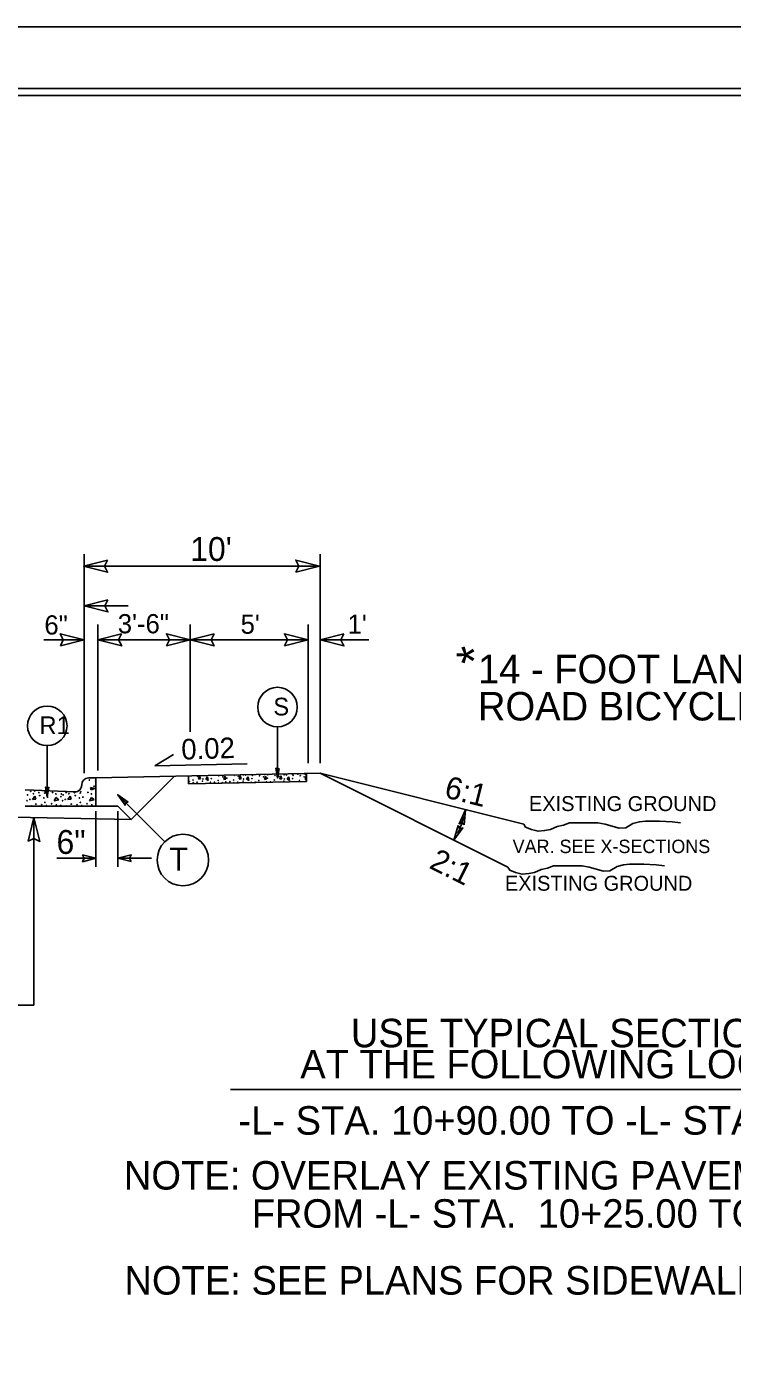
# Model space of a CAD drawing. Extents: x 573786 to 574032, y -53324 to -53148.
# Drawn here: x 573965.38 to 573991.09, y -53263.27 to -53214.45 of the extents above; entities that cross this region are included whole.
import ezdxf

# ---------------------------------------------------------------- set-up
doc = ezdxf.new("R2010")
doc.units = 0
for name, color, linetype in [('Default', 7, 'Continuous'), ('Prop Dimension Text', 7, 'Continuous'), ('Sheet Cutting Line CELL', 7, 'Continuous'), ('Sheet Plot Border Inside CELL', 7, 'Continuous'), ('Sheet Plot Border Outside CELL', 7, 'Continuous'), ('Sheet Typical CELL', 7, 'Continuous'), ('Typical Berm CELL', 7, 'Continuous'), ('Typical Berm Information CELL', 7, 'Continuous'), ('Typical Curb CELL', 7, 'Continuous'), ('Typical ID Circle CELL', 7, 'Continuous'), ('Typical Pavement Slope Information CELL', 7, 'Continuous'), ('Typical Slope Point Local CELL', 7, 'Continuous'), ('Typical Terminator CELL', 7, 'Continuous'), ('Typical Text ID Circle CELL', 7, 'Continuous'), ('Typical Text Label CELL', 7, 'Continuous')]:
    doc.layers.add(name, color=color, linetype=linetype)

# ---------------------------------------------------------------- blocks, each defined once
blk = doc.blocks.new('TERMINATOR')
at = {"layer": 'Typical Terminator CELL'}
blk.add_lwpolyline([(-0.469, 0.081), (0, 0), (-0.471, -0.083), (-0.411, 0)], close=True, dxfattribs=at)

msp = doc.modelspace()

# ---------------------------------------------------------------- linework, layer by layer
at = {"layer": 'Default'}
for points in [[(573989.198, -53243.465), (573988.895, -53243.421), (573988.442, -53243.4), (573988.139, -53243.4), (573987.923, -53243.4), (573987.707, -53243.421), (573987.469, -53243.486), (573987.21, -53243.638), (573986.973, -53243.659), (573986.67, -53243.573), (573986.454, -53243.508), (573986.195, -53243.465), (573985.892, -53243.465), (573985.655, -53243.465), (573985.417, -53243.465), (573985.158, -53243.465), (573984.942, -53243.551), (573984.704, -53243.594), (573984.466, -53243.702), (573984.25, -53243.746), (573984.012, -53243.767), (573983.775, -53243.702), (573983.559, -53243.616), (573983.494, -53243.508)], [(573988.618, -53245.032), (573988.316, -53244.988), (573987.862, -53244.967), (573987.56, -53244.967), (573987.344, -53244.967), (573987.127, -53244.988), (573986.89, -53245.053), (573986.631, -53245.205), (573986.393, -53245.226), (573986.09, -53245.14), (573985.874, -53245.075), (573985.615, -53245.032), (573985.313, -53245.032), (573985.075, -53245.032), (573984.837, -53245.032), (573984.578, -53245.032), (573984.362, -53245.118), (573984.124, -53245.161), (573983.887, -53245.269), (573983.671, -53245.313), (573983.433, -53245.334), (573983.195, -53245.269), (573982.979, -53245.183), (573982.914, -53245.075)]]:
    msp.add_lwpolyline(points, dxfattribs=at)
at = {"layer": 'Prop Dimension Text'}
for p, q in [((573967.47, -53241.655), (573967.47, -53233.673)), ((573976.067, -53241.285), (573976.067, -53233.673)), ((573967.47, -53234.106), (573976.052, -53234.105)), ((573967.47, -53235.551), (573969.076, -53235.55)), ((573967.971, -53241.548), (573967.971, -53236.228)), ((573971.339, -53240.145), (573971.338, -53236.228)), ((573975.637, -53241.285), (573975.637, -53236.228)), ((573966.004, -53236.792), (573967.47, -53236.792)), ((573967.971, -53236.792), (573975.637, -53236.792)), ((573976.067, -53236.792), (573977.84, -53236.792)), ((573971.676, -53241.747), (573971.641, -53241.869)), ((573971.713, -53241.855), (573971.676, -53241.747)), ((573971.905, -53241.862), (573971.963, -53241.781)), ((573971.963, -53241.781), (573971.995, -53241.912)), ((573972.595, -53241.762), (573972.56, -53241.885)), ((573972.632, -53241.871), (573972.595, -53241.762)), ((573973.158, -53241.747), (573973.122, -53241.869)), ((573973.194, -53241.855), (573973.158, -53241.747)), ((573973.386, -53241.862), (573973.445, -53241.781)), ((573973.445, -53241.781), (573973.476, -53241.912)), ((573974.077, -53241.762), (573974.041, -53241.885)), ((573974.114, -53241.871), (573974.077, -53241.762)), ((573974.639, -53241.747), (573974.604, -53241.869)), ((573974.676, -53241.855), (573974.639, -53241.747)), ((573974.868, -53241.862), (573974.926, -53241.781)), ((573974.926, -53241.781), (573974.958, -53241.912)), ((573975.558, -53241.762), (573975.523, -53241.885)), ((573975.569, -53241.794), (573975.558, -53241.762)), ((573971.342, -53242.037), (573971.342, -53242.037)), ((573971.342, -53242.037), (573971.342, -53242.037)), ((573971.641, -53241.869), (573971.713, -53241.855)), ((573971.995, -53241.912), (573971.905, -53241.862)), ((573972.56, -53241.885), (573972.632, -53241.871)), ((573973.122, -53241.869), (573973.194, -53241.855)), ((573973.476, -53241.912), (573973.386, -53241.862)), ((573974.041, -53241.885), (573974.114, -53241.871)), ((573974.604, -53241.869), (573974.676, -53241.855)), ((573974.958, -53241.912), (573974.868, -53241.862)), ((573975.523, -53241.885), (573975.569, -53241.876)), ((573965.642, -53250.111), (573965.641, -53243.269)), ((573967.903, -53245.07), (573967.903, -53243.039)), ((573968.701, -53245.07), (573968.701, -53243.039)), ((573967.903, -53244.753), (573966.471, -53244.753)), ((573969.921, -53244.753), (573968.701, -53244.753)), ((573965.642, -53250.111), (573957.762, -53250.111))]:
    msp.add_line(p, q, dxfattribs=at)
for centre in [(573971.609, -53241.77), (573972.383, -53241.745), (573972.528, -53241.785), (573972.67, -53241.833), (573972.946, -53241.729), (573973.09, -53241.77), (573973.359, -53241.722), (573973.603, -53241.727), (573973.865, -53241.745), (573974.009, -53241.785), (573974.151, -53241.833), (573974.165, -53241.711), (573974.427, -53241.729), (573974.572, -53241.77), (573974.764, -53241.709), (573974.84, -53241.722), (573975.066, -53241.691), (573975.084, -53241.727), (573975.256, -53241.687), (573975.346, -53241.745), (573975.491, -53241.785), (573975.536, -53241.696), (573971.302, -53241.964), (573971.437, -53241.901), (573971.451, -53241.995), (573971.586, -53241.982), (573971.785, -53241.941), (573971.801, -53241.862), (573972.076, -53241.984), (573972.108, -53241.849), (573972.221, -53241.98), (573972.356, -53241.916), (573972.505, -53241.998), (573972.638, -53241.968), (573972.783, -53241.964), (573972.919, -53241.901), (573972.932, -53241.995), (573973.068, -53241.982), (573973.266, -53241.941), (573973.282, -53241.862), (573973.558, -53241.984), (573973.589, -53241.849), (573973.702, -53241.98), (573973.838, -53241.916), (573974.12, -53241.968), (573974.264, -53241.964), (573974.4, -53241.901), (573974.748, -53241.941), (573974.764, -53241.862), (573975.071, -53241.849), (573975.319, -53241.916)]:
    msp.add_circle(centre, 0.00635, dxfattribs=at)
for centre, radius, start, end in [((573973.282, -53241.709), 0.00635, 191.5586, 350.8341), ((573974.054, -53241.696), 0.00635, 160.0148, 22.378), ((573972.37, -53242.011), 0.00635, 319.9083, 222.4844), ((573976.738, -53241.892), 4.763, 335.7343, 343.6673)]:
    msp.add_arc(centre, radius, start, end, dxfattribs=at)
at = {"layer": 'Sheet Cutting Line CELL'}
msp.add_line((574013.401, -53214.447), (573845.001, -53214.447), dxfattribs=at)
at = {"layer": 'Sheet Plot Border Inside CELL'}
msp.add_lwpolyline([(574012.951, -53216.692), (573846.301, -53216.692), (573846.301, -53322.202), (574012.951, -53322.202)], close=True, dxfattribs=at)
at = {"layer": 'Sheet Plot Border Outside CELL'}
msp.add_lwpolyline([(574013.401, -53214.447), (573845.001, -53214.447), (573845.001, -53324.447), (574013.401, -53324.447)], close=True, dxfattribs=at)
at = {"layer": 'Sheet Typical CELL'}
msp.add_lwpolyline([(574011.701, -53216.947), (573861.701, -53216.947), (573861.701, -53321.947), (574011.701, -53321.947)], close=True, dxfattribs=at)
at = {"layer": 'Typical Berm CELL'}
for p, q in [((573976.067, -53241.651), (573967.903, -53241.822)), ((573975.569, -53241.949), (573971.27, -53242.038))]:
    msp.add_line(p, q, dxfattribs=at)
at = {"layer": 'Typical Curb CELL'}
for p, q in [((573967.903, -53241.822), (573967.634, -53241.822)), ((573967.903, -53242.855), (573967.903, -53241.822)), ((573965.319, -53242.253), (573967.128, -53242.328)), ((573967.386, -53242.081), (573967.386, -53242.07)), ((573967.706, -53242.167), (573967.723, -53242.26)), ((573967.865, -53242.213), (573967.706, -53242.167)), ((573967.723, -53242.26), (573967.865, -53242.213)), ((573965.588, -53242.608), (573965.678, -53242.484)), ((573965.713, -53242.602), (573965.588, -53242.608)), ((573965.678, -53242.484), (573965.713, -53242.602)), ((573966.38, -53242.661), (573966.444, -53242.542)), ((573966.551, -53242.62), (573966.38, -53242.661)), ((573966.444, -53242.542), (573966.551, -53242.62)), ((573966.88, -53242.608), (573966.968, -53242.484)), ((573967.004, -53242.601), (573966.88, -53242.608)), ((573966.968, -53242.484), (573967.004, -53242.601)), ((573967.67, -53242.661), (573967.735, -53242.542)), ((573967.842, -53242.62), (573967.67, -53242.661)), ((573967.735, -53242.542), (573967.842, -53242.62)), ((573967.903, -53242.855), (573965.319, -53242.856))]:
    msp.add_line(p, q, dxfattribs=at)
for centre in [(573965.524, -53242.313), (573965.671, -53242.296), (573966.055, -53242.325), (573967.346, -53242.325), (573967.665, -53241.9), (573967.836, -53242.125), (573967.889, -53241.936), (573965.395, -53242.655), (573965.412, -53242.442), (573965.495, -53242.608), (573965.624, -53242.401), (573965.713, -53242.779), (573965.825, -53242.361), (573965.854, -53242.466), (573965.925, -53242.802), (573966.008, -53242.554), (573966.037, -53242.377), (573966.043, -53242.714), (573966.138, -53242.525), (573966.285, -53242.767), (573966.32, -53242.355), (573966.444, -53242.407), (573966.462, -53242.808), (573966.627, -53242.507), (573966.645, -53242.407), (573966.686, -53242.655), (573966.703, -53242.442), (573966.786, -53242.608), (573966.815, -53242.357), (573966.915, -53242.401), (573967.004, -53242.779), (573967.116, -53242.361), (573967.145, -53242.466), (573967.216, -53242.802), (573967.299, -53242.554), (573967.328, -53242.377), (573967.334, -53242.714), (573967.429, -53242.525), (573967.576, -53242.767), (573967.612, -53242.355), (573967.736, -53242.407), (573967.753, -53242.808), (573965.548, -53242.849), (573966.102, -53242.832), (573966.621, -53242.826), (573966.839, -53242.849), (573967.393, -53242.832)]:
    msp.add_circle(centre, 0.00829, dxfattribs=at)
for centre, start, end in [((573967.634, -53242.07), 90.0023, 180.0023), ((573967.138, -53242.081), 267.6179, 0.0023)]:
    msp.add_arc(centre, 0.248, start, end, dxfattribs=at)
at = {"layer": 'Typical ID Circle CELL'}
for p, q in [((573974.517, -53239.963), (573974.517, -53241.827)), ((573966.128, -53240.646), (573966.128, -53242.51)), ((573970.408, -53244.153), (573968.694, -53242.439))]:
    msp.add_line(p, q, dxfattribs=at)
for centre, radius in [((573974.517, -53239.242), 0.721), ((573966.128, -53239.925), 0.721), ((573971.07, -53244.816), 0.938)]:
    msp.add_circle(centre, radius, dxfattribs=at)
at = {"layer": 'Typical Pavement Slope Information CELL'}
for q in [(573970.723, -53240.972), (573973.407, -53241.311)]:
    msp.add_line((573970.05, -53241.379), q, dxfattribs=at)
at = {"layer": 'Typical Slope Point Local CELL'}
for p, q in [((573969.184, -53243.338), (573970.759, -53241.762)), ((573971.27, -53242.038), (573971.27, -53241.752)), ((573975.569, -53241.949), (573975.569, -53241.662)), ((573976.067, -53241.651), (573983.494, -53243.508)), ((573976.067, -53241.651), (573982.914, -53245.075)), ((573961.335, -53243.175), (573969.184, -53243.338)), ((573967.903, -53242.855), (573968.701, -53242.855)), ((573968.701, -53242.855), (573969.184, -53243.338))]:
    msp.add_line(p, q, dxfattribs=at)
at = {"layer": 'Typical Terminator CELL'}
for points in [[(573974.578, -53241.476), (573974.517, -53241.827), (573974.455, -53241.474), (573974.517, -53241.519)], [(573966.188, -53242.158), (573966.128, -53242.51), (573966.065, -53242.156), (573966.128, -53242.201)], [(573969.072, -53242.707), (573968.694, -53242.439), (573968.961, -53242.822), (573968.977, -53242.723)], [(573981.322, -53243.537), (573981.363, -53242.987), (573981.136, -53243.494), (573981.247, -53243.45)], [(573981.102, -53243.561), (573980.942, -53244.09), (573981.273, -53243.644), (573981.156, -53243.663)]]:
    msp.add_lwpolyline(points, close=True, dxfattribs=at)
at = {"layer": 'Typical Text Label CELL'}
msp.add_line((573972.808, -53253.184), (574002.053, -53253.183), dxfattribs=at)

# ---------------------------------------------------------------- block references
at = {"layer": 'Prop Dimension Text'}
for p, xscale, yscale, rotation in [((573967.454, -53234.106), 1.8461659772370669, -2.649824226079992, -179.99768562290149), ((573976.052, -53234.105), 1.8461659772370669, -2.649824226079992, 0.002314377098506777), ((573967.47, -53235.551), 1.8461659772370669, -2.649824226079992, -179.99768562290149), ((573967.47, -53236.792), 1.8461659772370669, -2.649824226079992, 0.002314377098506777), ((573967.971, -53236.792), 1.8461659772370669, -2.649824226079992, -179.99768562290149), ((573971.338, -53236.792), 1.8461659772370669, -2.649824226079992, 0.002314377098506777), ((573971.338, -53236.792), 1.8461659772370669, -2.649824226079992, -179.99768562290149), ((573975.637, -53236.792), 1.8461659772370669, -2.649824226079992, 0.002314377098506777), ((573976.067, -53236.792), 1.8461659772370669, -2.649824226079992, -179.99768562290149), ((573965.641, -53243.269), 1.846165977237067, 2.6498242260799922, 90.0023143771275), ((573967.903, -53244.753), 1.038468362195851, 1.4905261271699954, 0.0023143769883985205), ((573968.701, -53244.753), 1.038468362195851, 1.4905261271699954, -179.99768562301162)]:
    msp.add_blockref('TERMINATOR', p, dxfattribs=dict(at, xscale=xscale, yscale=yscale, rotation=rotation))

# ---------------------------------------------------------------- texts
for s, height, rotation, p in [("10'", 0.8705, 0.0023, (573971.336, -53233.916)), ('6"', 0.7, 0.0023, (573966.023, -53236.598)), ('3\'-6"', 0.7, 0.0023, (573968.698, -53236.553)), ("5'", 0.7, 0.0023, (573973.174, -53236.571)), ("1'", 0.7, 0.0023, (573977.072, -53236.571)), ('*', 1.28, 90, (573982.323, -53237.672)), ('6"', 0.8705, 0.0023, (573966.465, -53244.593))]:
    msp.add_text(s, height=height, rotation=rotation, dxfattribs=at).set_placement(p)
for s, p in [('14 - FOOT LANE USED FOR SHARE THE ', (573981.822, -53238.374)), ('ROAD BICYCLE ACCOMODATION.', (573981.822, -53239.73))]:
    msp.add_text(s, height=1.03895, dxfattribs=at).set_placement(p)
at = {"layer": 'Typical Berm Information CELL'}
msp.add_text('0.02', height=0.75, rotation=1.8107, dxfattribs=at).set_placement((573971.024, -53241.158))
at = {"layer": 'Typical Slope Point Local CELL'}
for s, height, rotation, p in [('6:1', 0.8124, 345.9643, (573980.562, -53242.525)), ('EXISTING GROUND', 0.54395, 359.9977, (573983.682, -53243.032)), ('VAR. SEE X-SECTIONS', 0.48956, 359.9977, (573983.085, -53244.564)), ('2:1', 0.8124, 333.4355, (573980.005, -53245.092)), ('EXISTING GROUND', 0.54395, 359.9977, (573982.804, -53245.936))]:
    msp.add_text(s, height=height, rotation=rotation, dxfattribs=at).set_placement(p)
at = {"layer": 'Typical Text ID Circle CELL'}
for s, height, p in [('S', 0.646, (573974.366, -53239.547)), ('R1', 0.6456, (573965.843, -53240.229))]:
    msp.add_text(s, height=height, rotation=360, dxfattribs=at).set_placement(p)
msp.add_text('T', height=0.839, dxfattribs=at).set_placement((573970.572, -53245.202))
at = {"layer": 'Typical Text Label CELL'}
for s, p in [('USE TYPICAL SECTION NO. 1', (573977.191, -53251.643)), ('AT THE FOLLOWING LOCATIONS:', (573975.347, -53252.775)), ('-L- STA. 10+90.00 TO -L- STA. 13+75.00', (573973.093, -53254.827)), ('NOTE: OVERLAY EXISTING PAVEMENT WITH 1', (573968.918, -53256.828)), ('FROM -L- STA.  10+25.00 TO -L- STA.  10+90.00', (573973.579, -53258.219)), ('NOTE: SEE PLANS FOR SIDEWALK LIMITS', (573968.939, -53260.657))]:
    msp.add_text(s, height=1.03895, rotation=0.0023, dxfattribs=at).set_placement(p)

doc.saveas('drawing.dxf')
